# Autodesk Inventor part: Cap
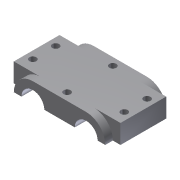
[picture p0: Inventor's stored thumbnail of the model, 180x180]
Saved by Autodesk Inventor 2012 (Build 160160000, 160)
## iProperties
Shininess: 77.0
Length Units: 11269
Angle Units: 11279
Time Units: 11290
Mass Units: 11283
Length Display Precision: 3
Angle Display Precision: 2
Created: 2002-02
Part Number: Cap
Document SubType Name: Modeling
Designer: ***
Density: 1 g/cm^3
Material: Default
Density: 0.0
Volumn: 0.0
Area: 0.0
PropertySet Name: Model Information
Control State: 0
Master: False
Checked Out: False
Author: ***
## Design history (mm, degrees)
sketch "Sketch2"
  geometry: L1 (-17.5, 12.5)-(17.5, 12.5); L2 (30, 0)-(25, 0); L3 (10, 0)-(-10, 0); L4 (-25, 0)-(-30, 0); A1 r 12.5 centre (-17.5, 0) between (-17.5, 12.5) and (-30, 0); A2 r 12.5 centre (17.5, 0) between (30, 0) and (17.5, 12.5); A3 r 7.5 centre (17.5, 0) between (25, 0) and (10, 0); A4 r 7.5 centre (-17.5, 0) between (-10, 0) and (-25, 0)
  constraints: 8 end point, 8 point on circle, 4 centre point, 3 horizontal, 3 parallel, 2 coincident, 2 equal radius, 2 tangent
  dimensions: "d0" = 12.5 radius of A1; "d1" = 7.5 radius of A4; "d2" = 35 distance of A1.centre A2.centre; "d3" = 12.5 distance between parallel lines of L1 L3
extrude "Extrusion1" new body sketch "Sketch2" stored distance "d4" = 40; taper "d5" = 0 deg
workplane "Work Plane1"
sketch "Sketch3"
  geometry: L1 (-15, 12.5)-(15, 12.5); L2 (15, 12.5)-(15, 0); L3 (15, 0)-(-15, 0); L4 (-15, 0)-(-15, 12.5); L5 (-20, 0)-(20, 0) reference; L6 (-20, 12.5)-(20, 12.5) reference; L7 (20, 12.5)-(20, 0) reference
  constraints: 8 end point, 2 collinear, 2 parallel, 1 horizontal, 1 perpendicular
  dimensions: "d7" = 30 distance of L2.end L3.end; "d8" = 5 distance between parallel lines of L7 L2
extrude "Extrusion2" join sketch "Sketch3" stored distance "d9" = 40; taper "d10" = 0 deg
mirror "Mirror1"
sketch "Sketch4"
  geometry: L1 (-17.5, -35)-(0, -35) reference; L2 (-17.5, -35)-(-17.5, -5) reference; 1 further point
  dimensions: "d12" = 7.5 distance from line of L1 point (-12.5, -27.5); "d13" = 5 distance from line of L2 point (-12.5, -27.5)
hole "Hole1" sketch "Sketch4" at (-12.5, -27.5) diameter "d14" = 4.5; stored, may be unused: countersink angle "d18" = 82 deg, drill point angle "d20" = 118 deg; dims "d15" = 6, "d16" = 4, "d17" = 2, "d19" = 8
pattern_linear "Rectangular Pattern1" dims "d23" = 60, "d26" = 15
sketch "Sketch5"
  geometry: L1 (0, -40)-(35, -40) reference; L2 (-17.5, -35)-(-17.5, -5) reference; 1 further point
  dimensions: "d27" = 5 distance from line of L1 point (17.5, -35); "d28" = 35 distance from line of L2 point (17.5, -35)
hole "Hole2" sketch "Sketch5" at (17.5, -35) diameter "d29" = 4.5; stored, may be unused: countersink angle "d33" = 82 deg, drill point angle "d35" = 118 deg; dims "d30" = 6, "d31" = 4, "d32" = 2, "d34" = 8
pattern_linear "Rectangular Pattern2" dims "d38" = 30
body "Solid1"
other parameters: "d11" = 35
